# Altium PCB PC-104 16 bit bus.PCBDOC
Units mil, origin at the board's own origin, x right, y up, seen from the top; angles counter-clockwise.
Board outline 3550 x 3775 mil, 10 copper layers (TopLayer, MidLayer1, MidLayer2, MidLayer3, MidLayer4, MidLayer5, MidLayer6, MidLayer7, MidLayer8, BottomLayer); 2 components, 1 nets, 108 pads, 0 vias.
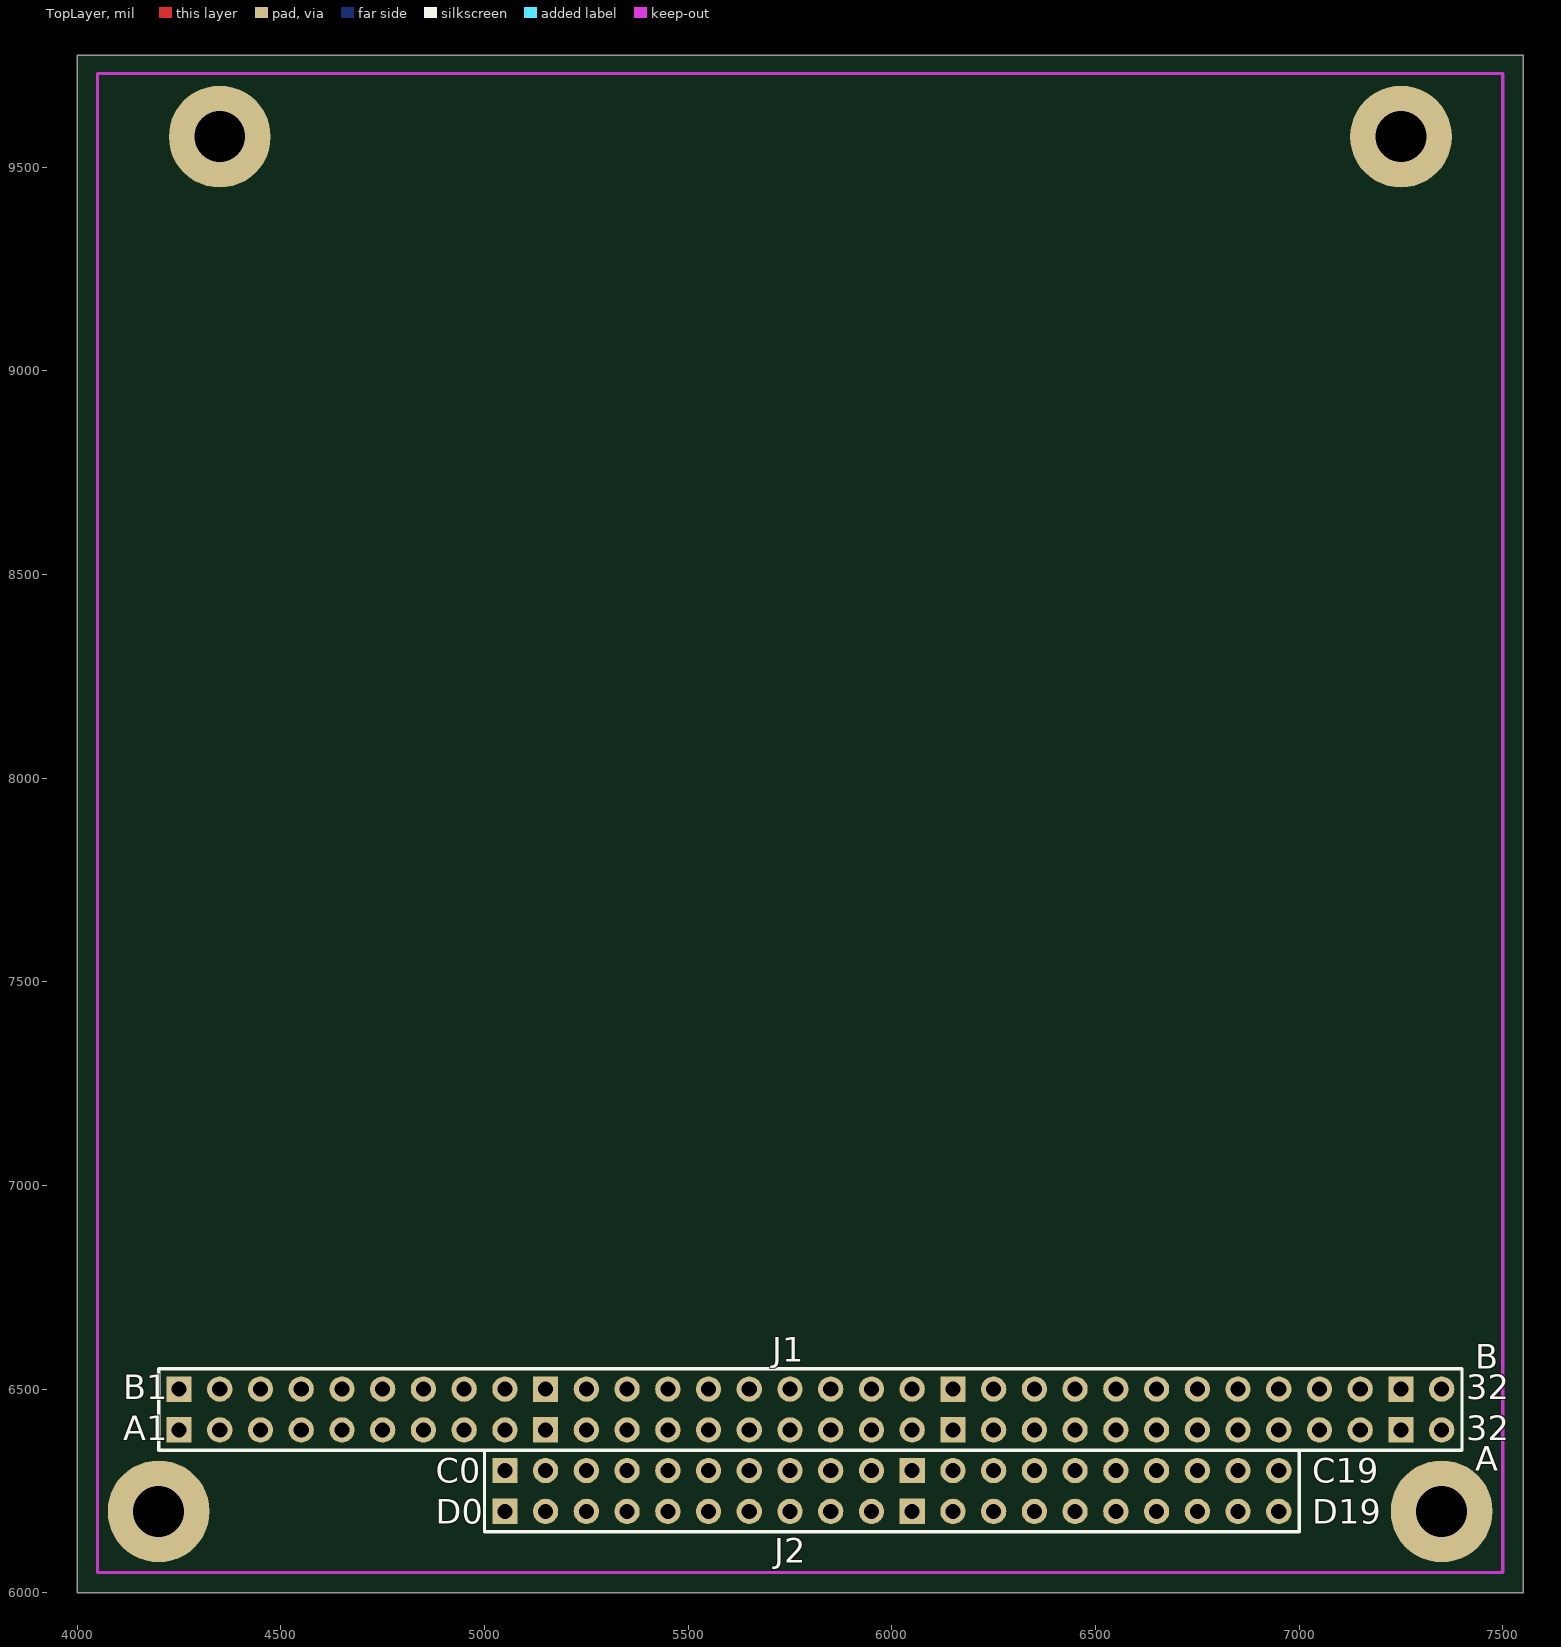
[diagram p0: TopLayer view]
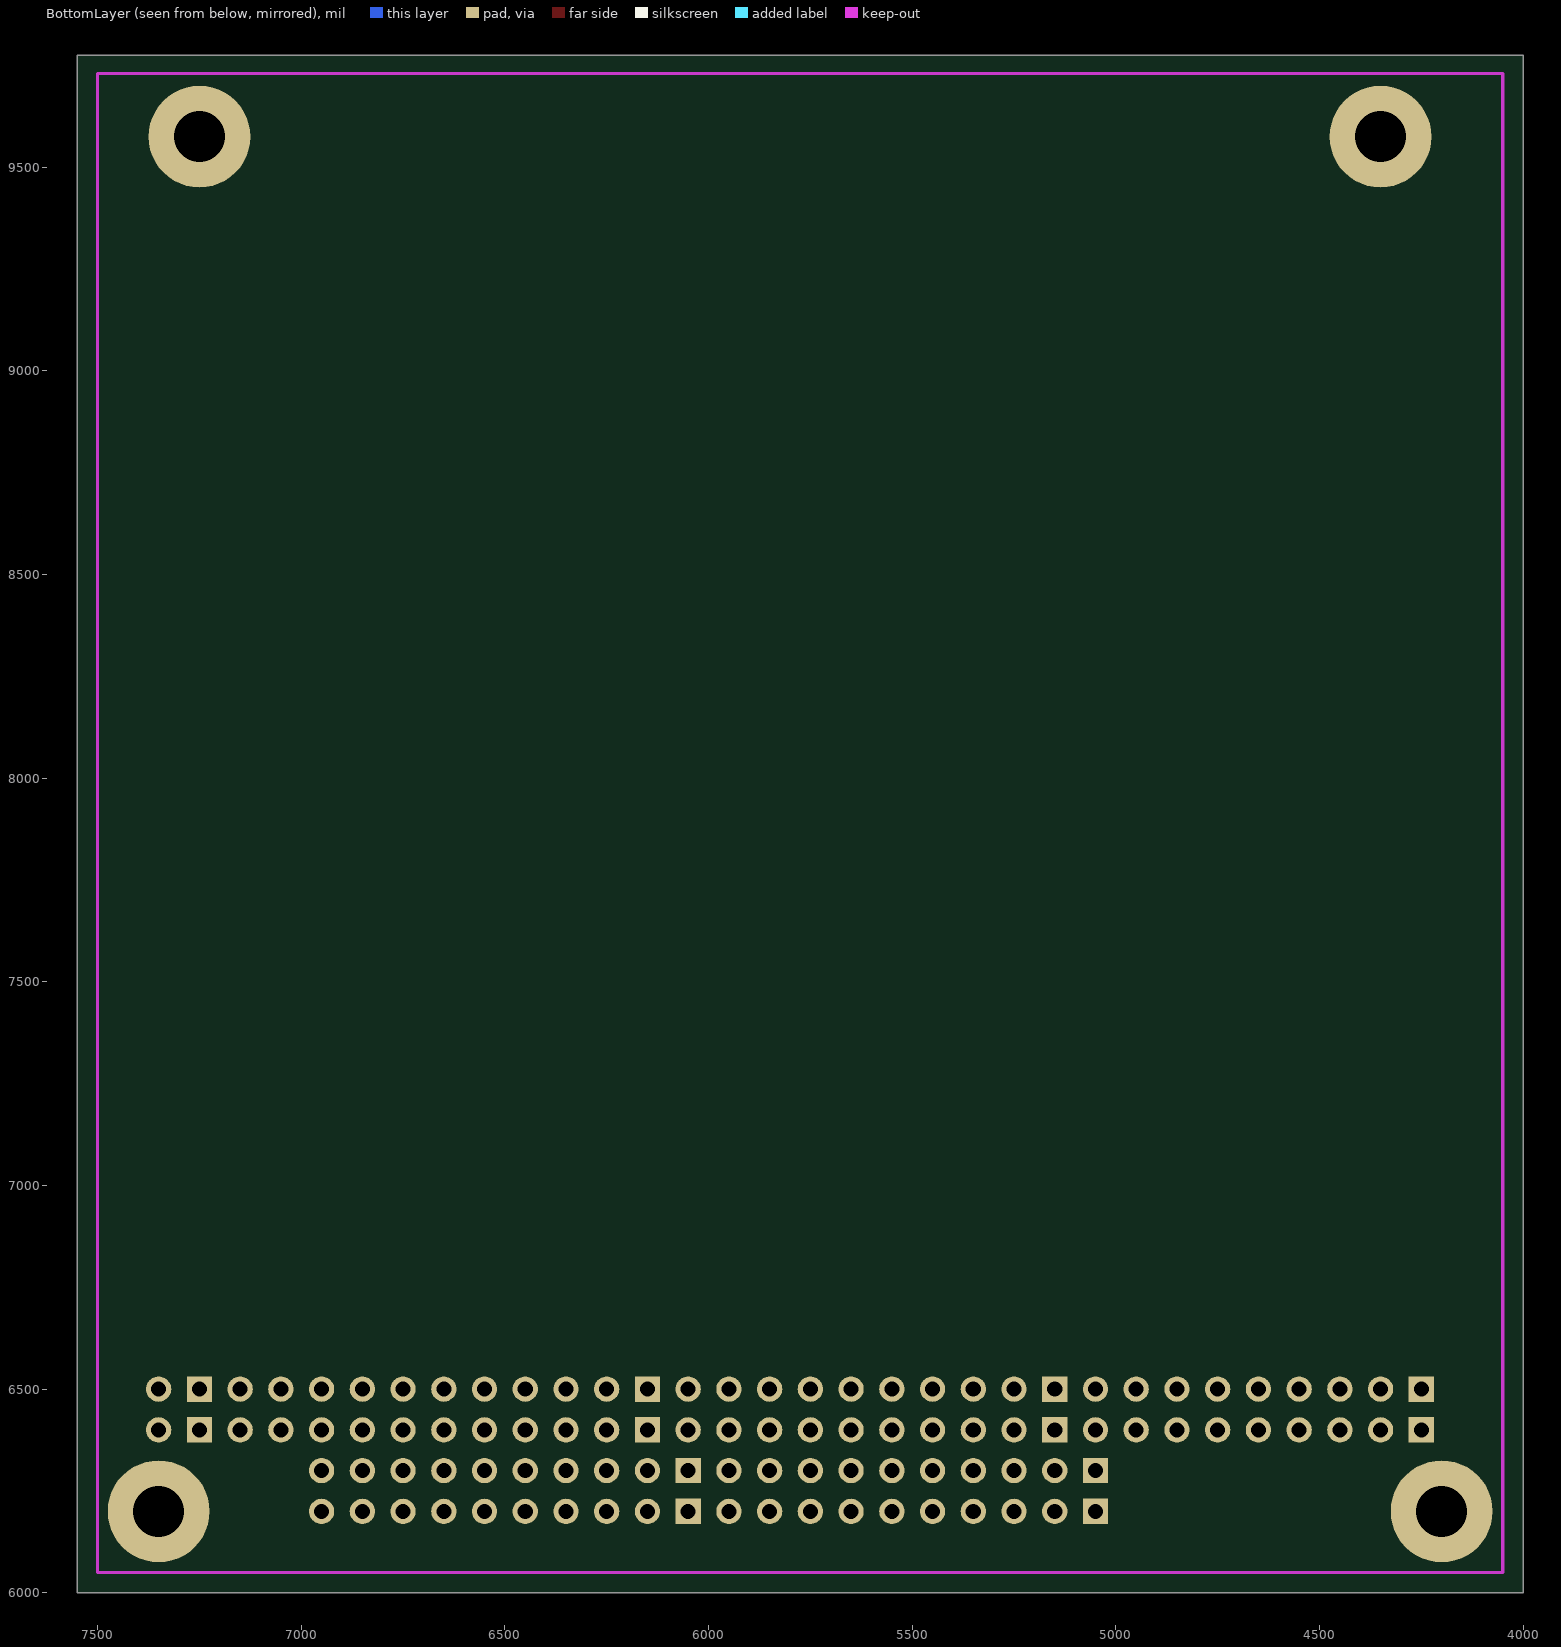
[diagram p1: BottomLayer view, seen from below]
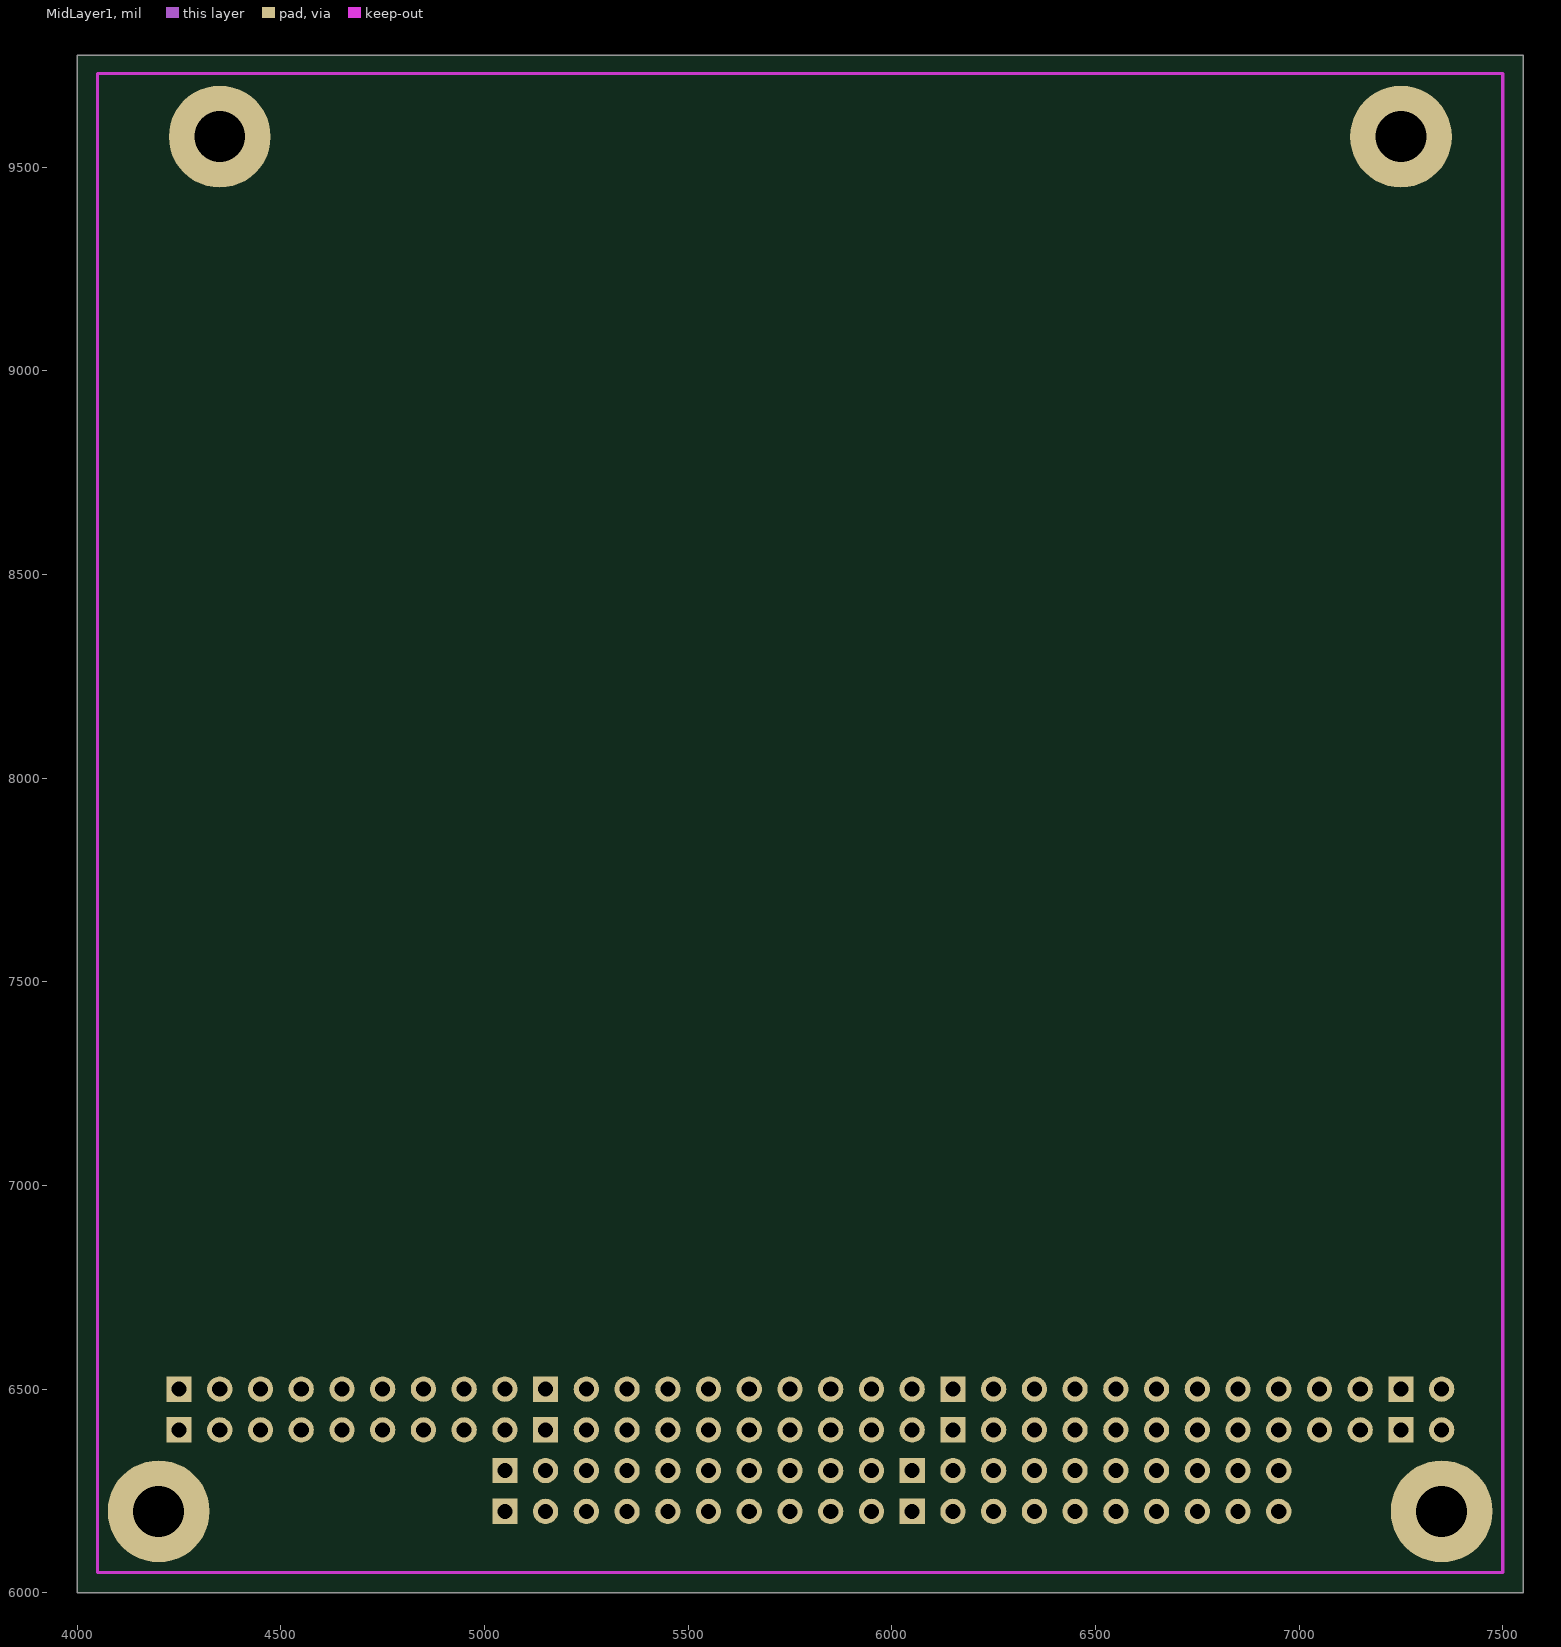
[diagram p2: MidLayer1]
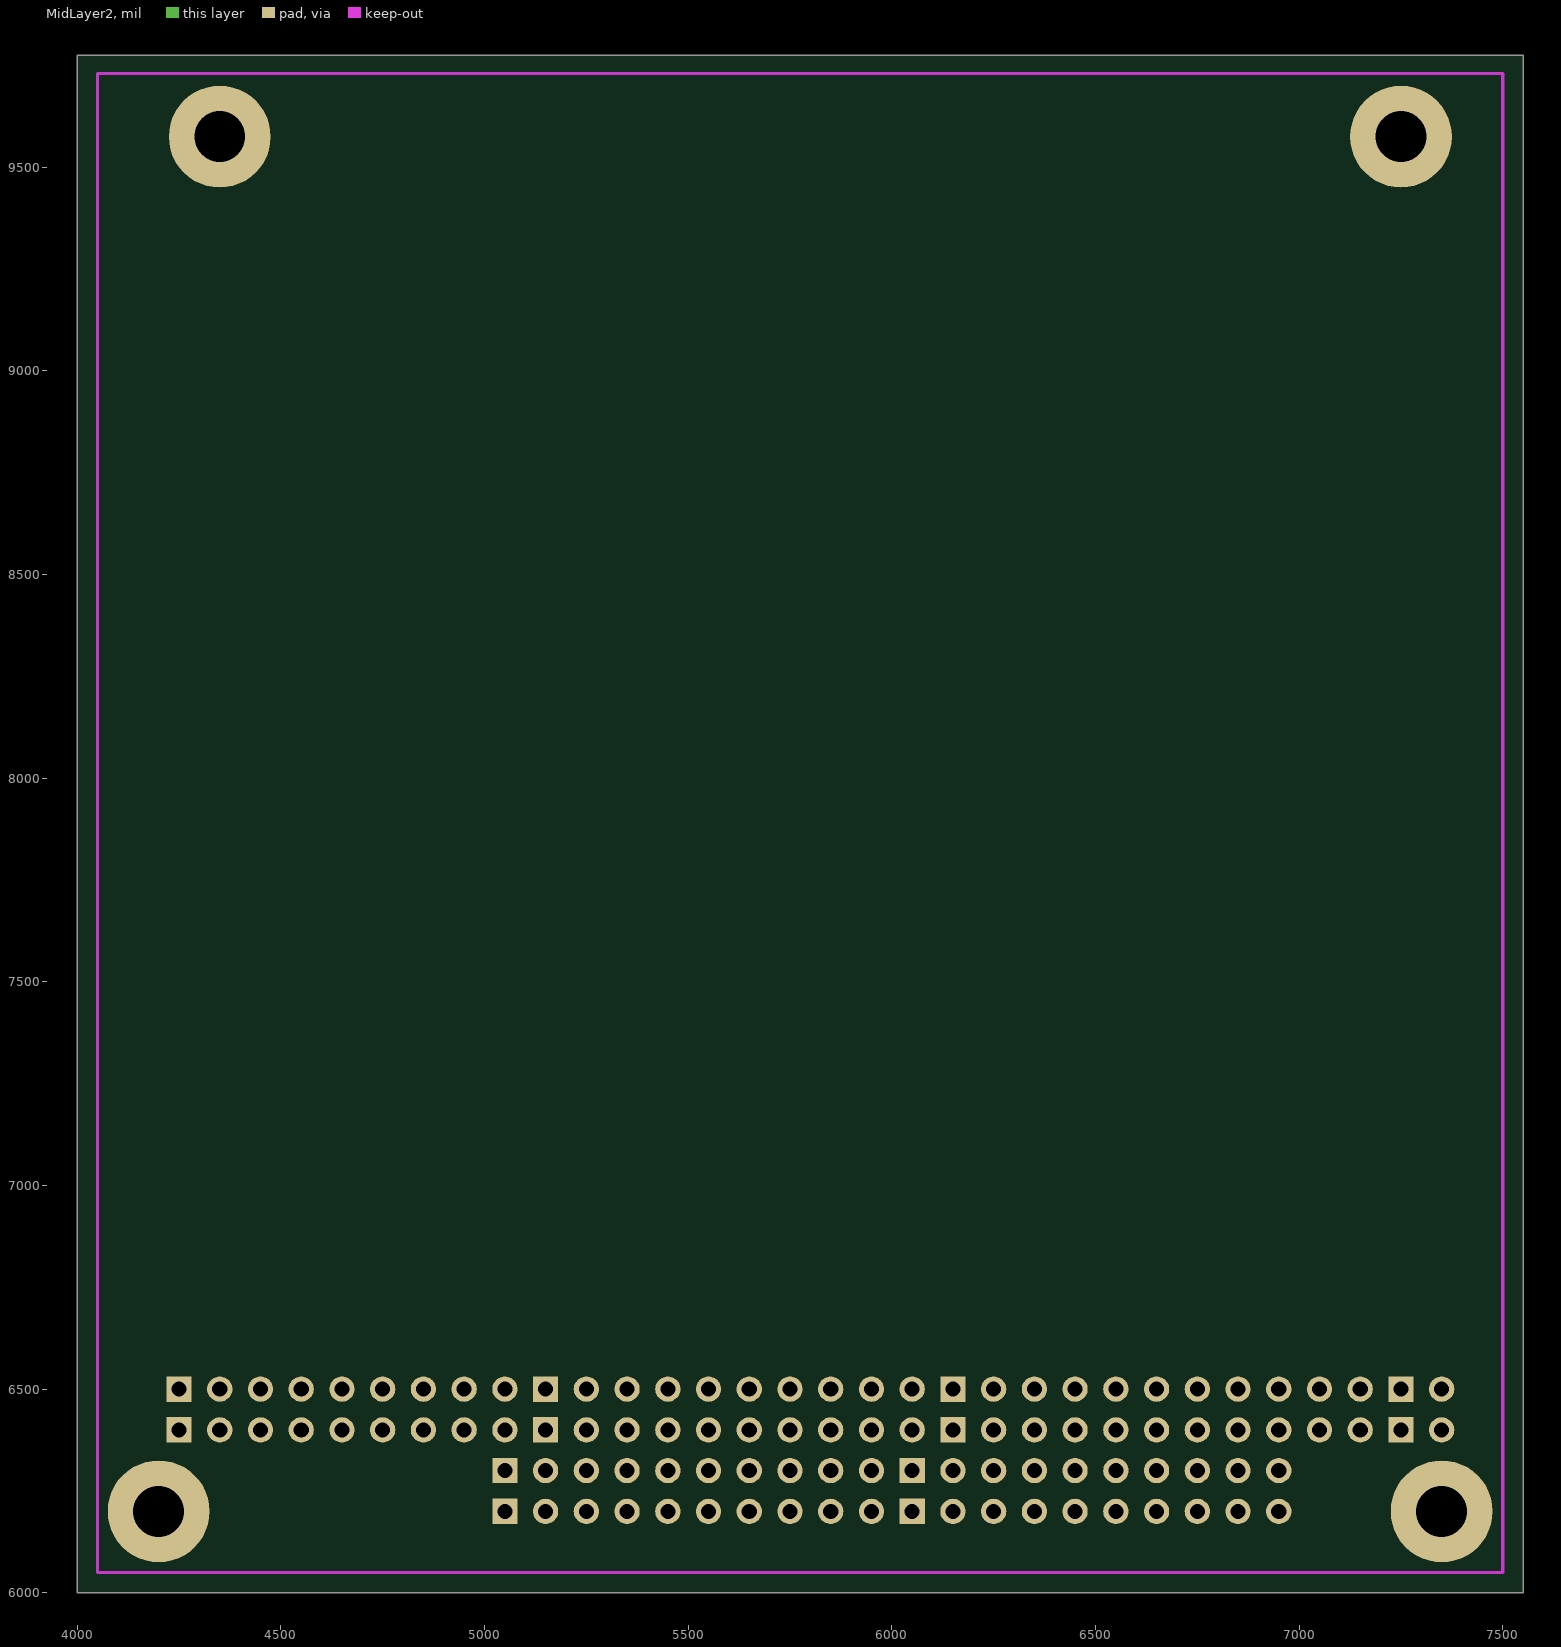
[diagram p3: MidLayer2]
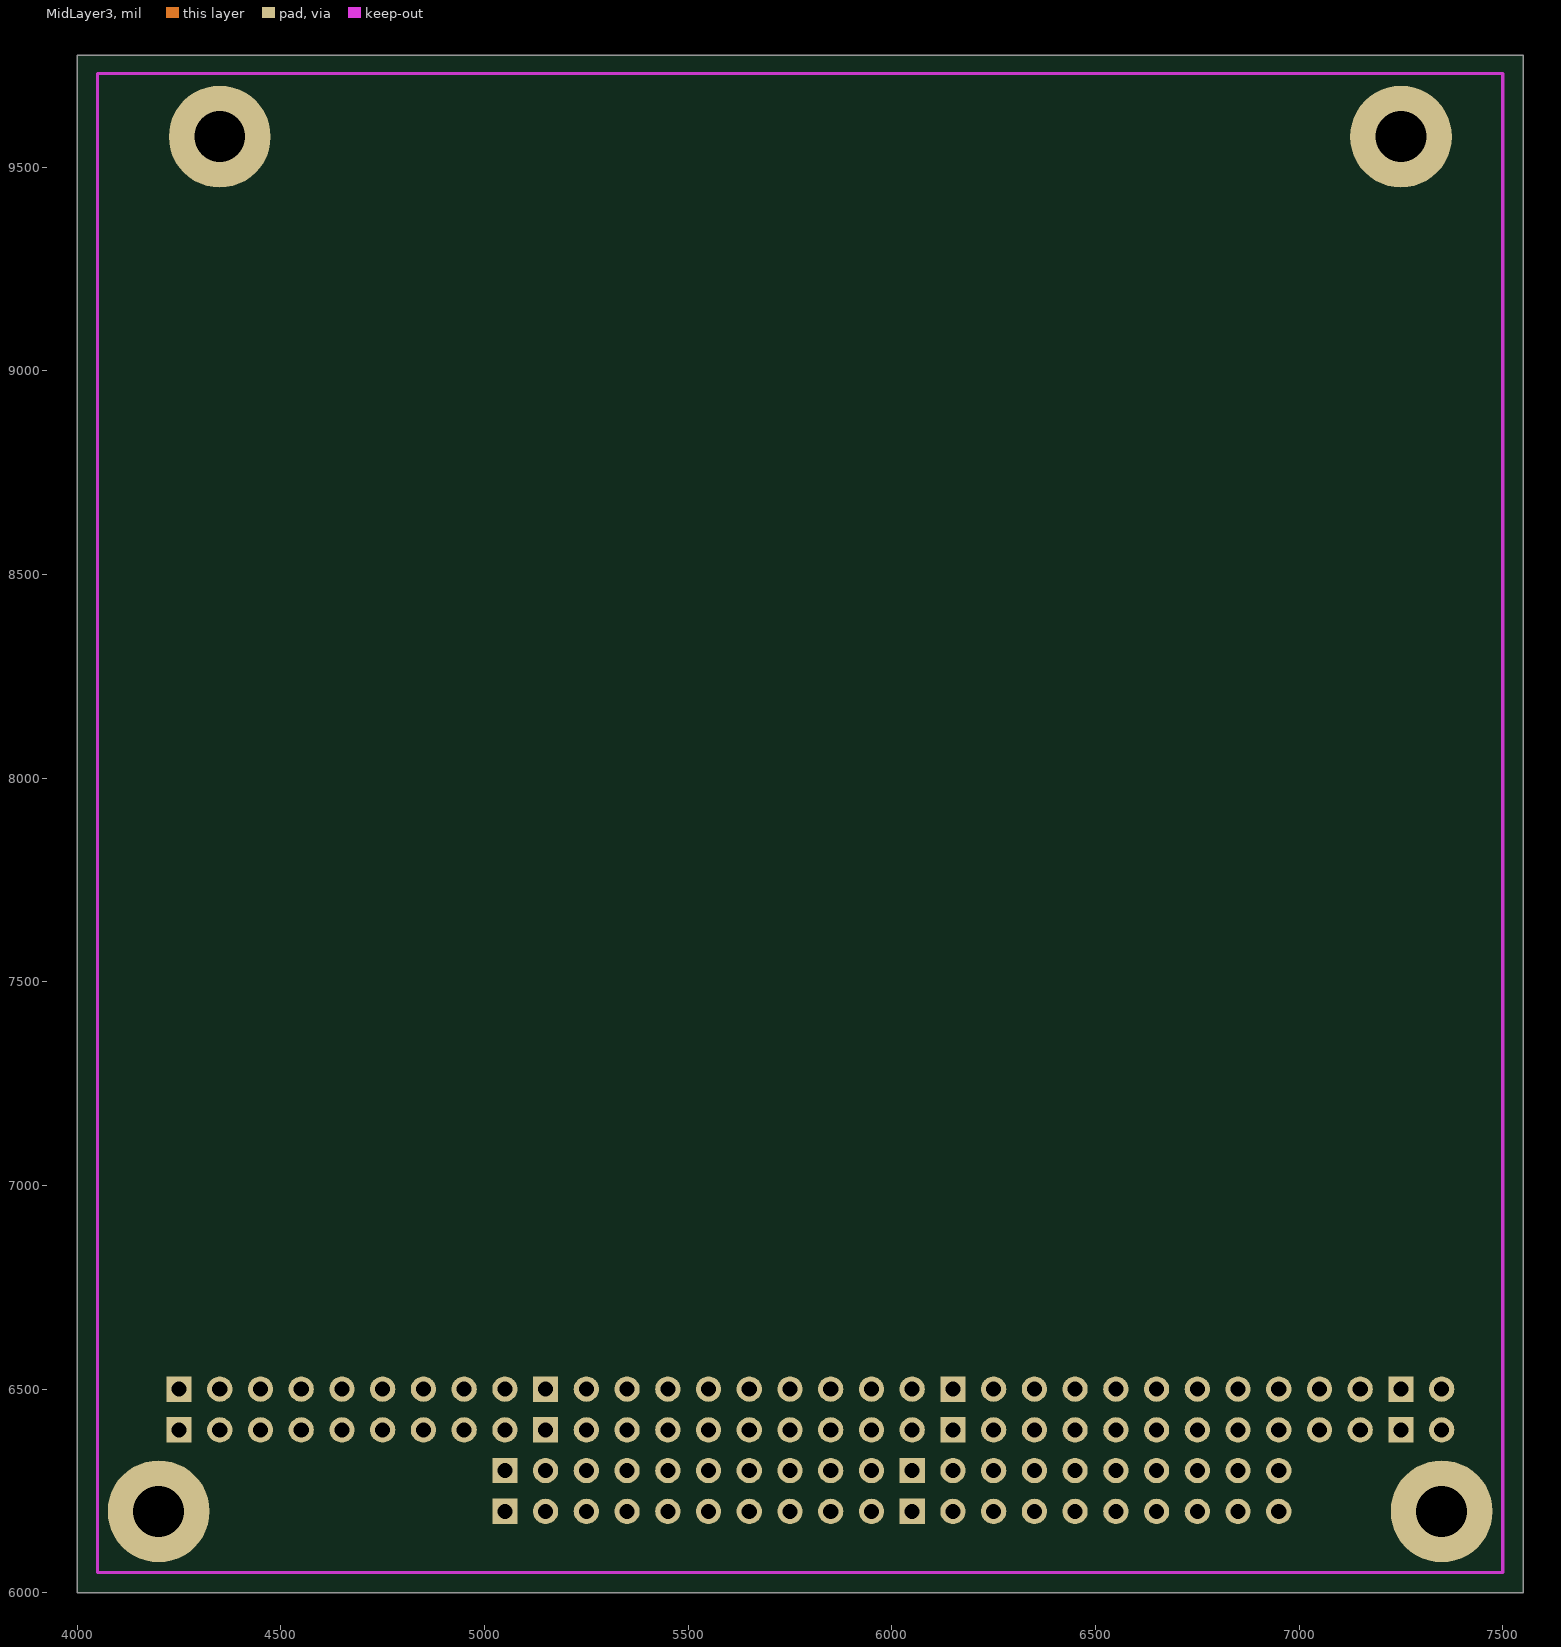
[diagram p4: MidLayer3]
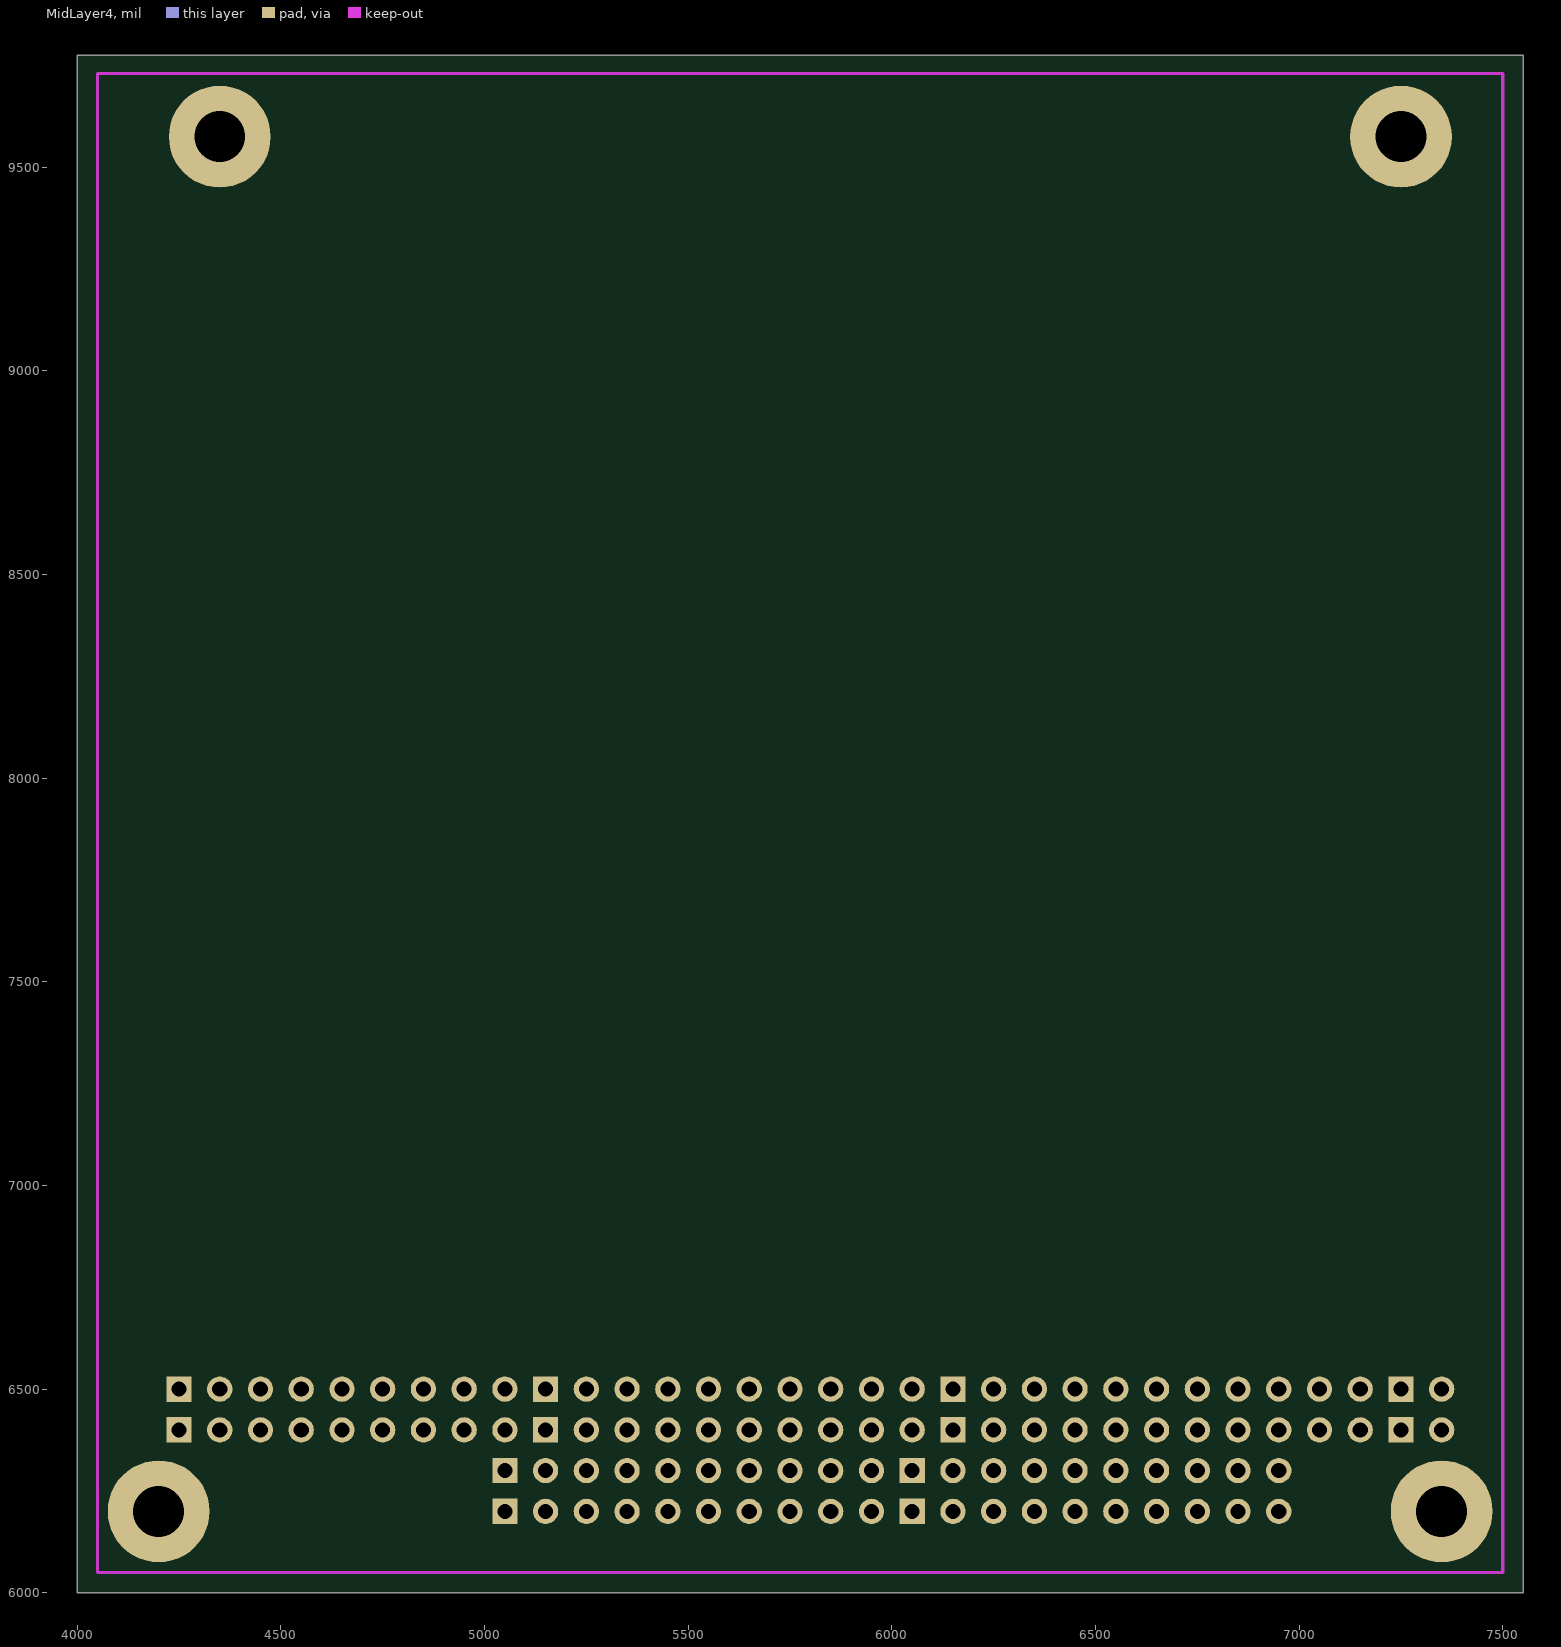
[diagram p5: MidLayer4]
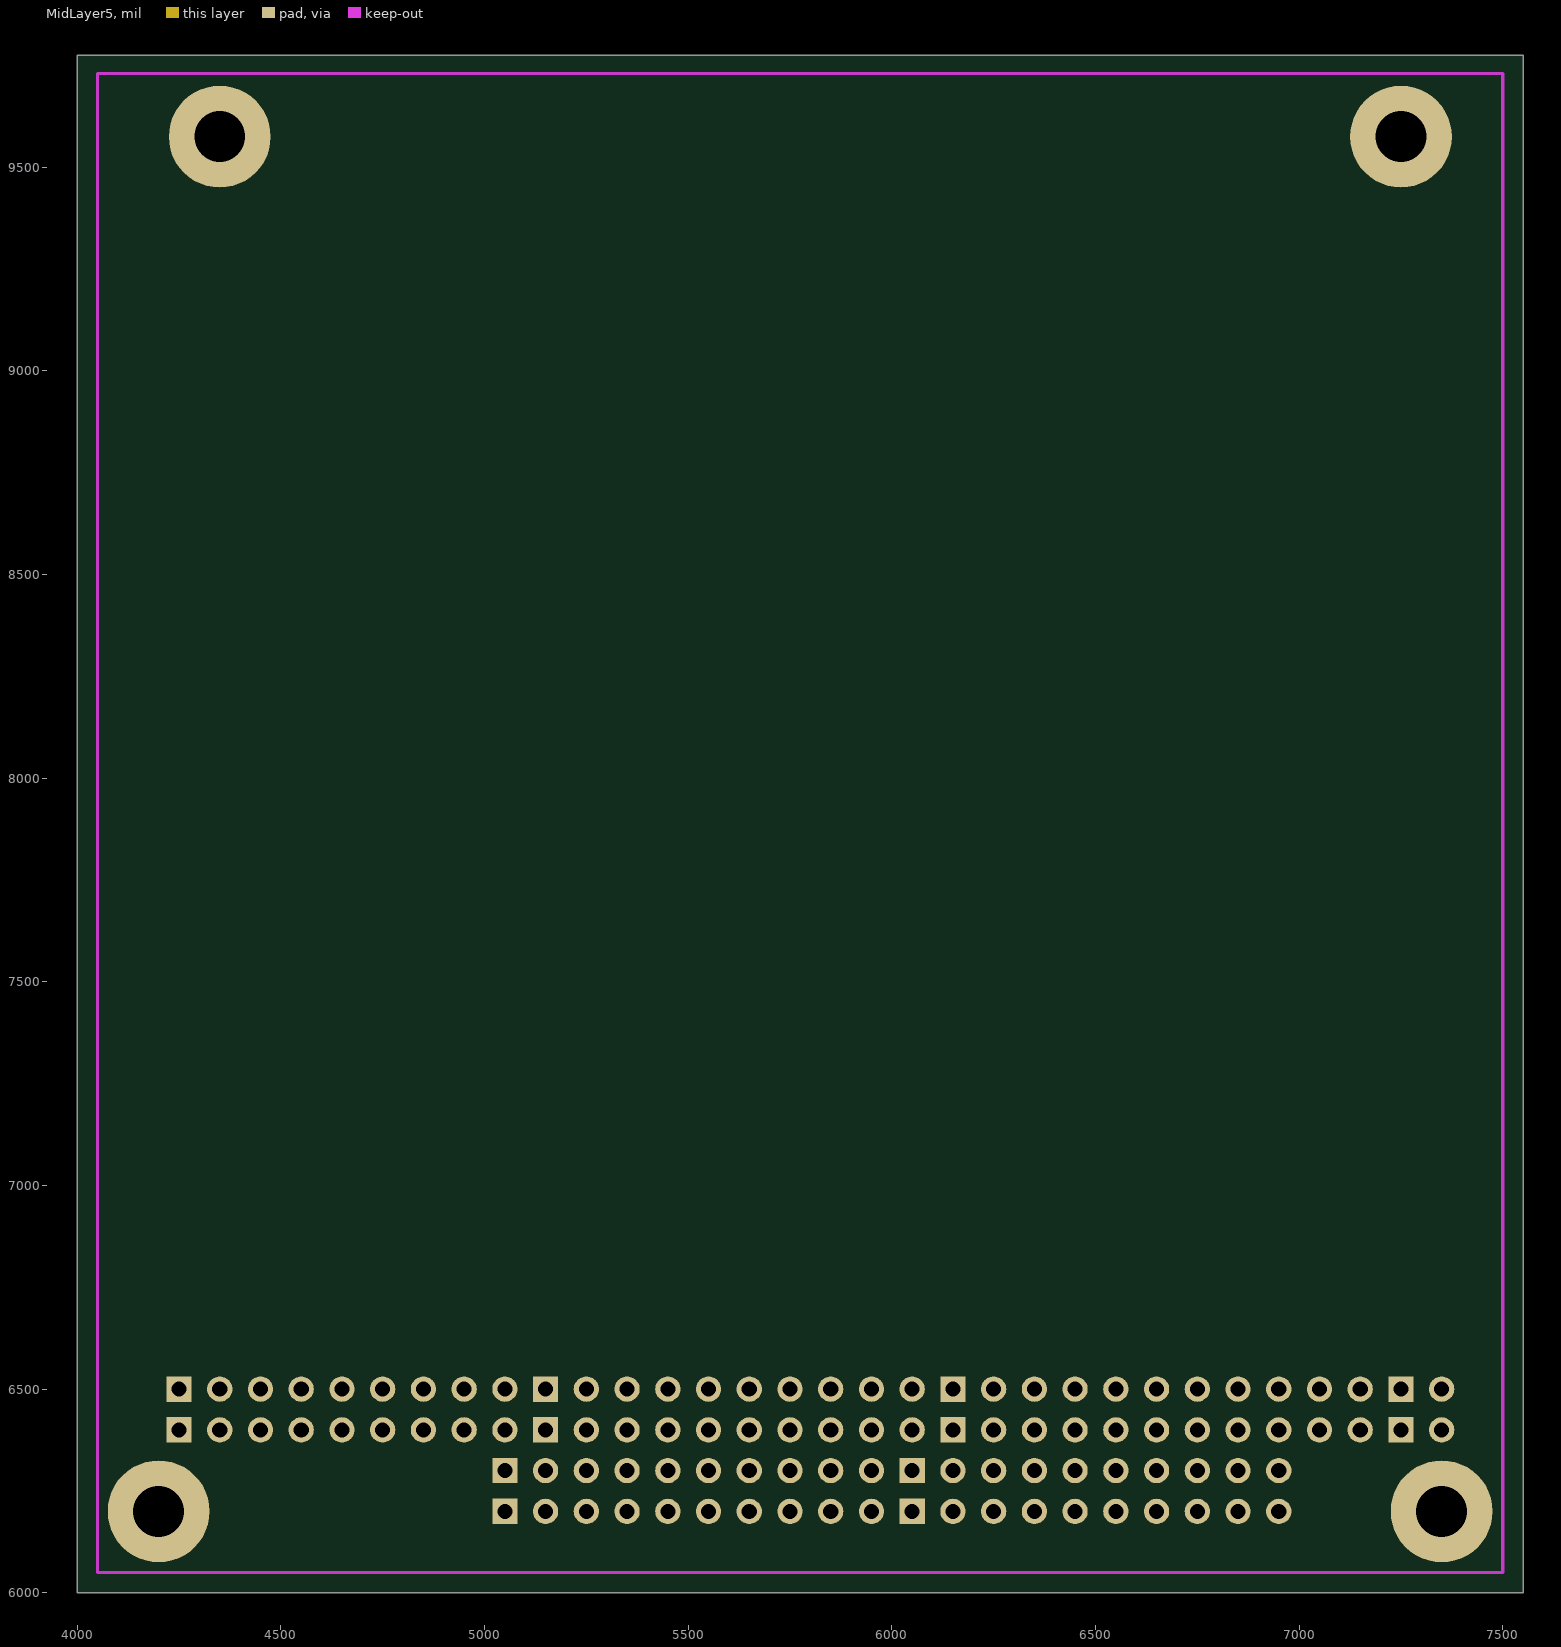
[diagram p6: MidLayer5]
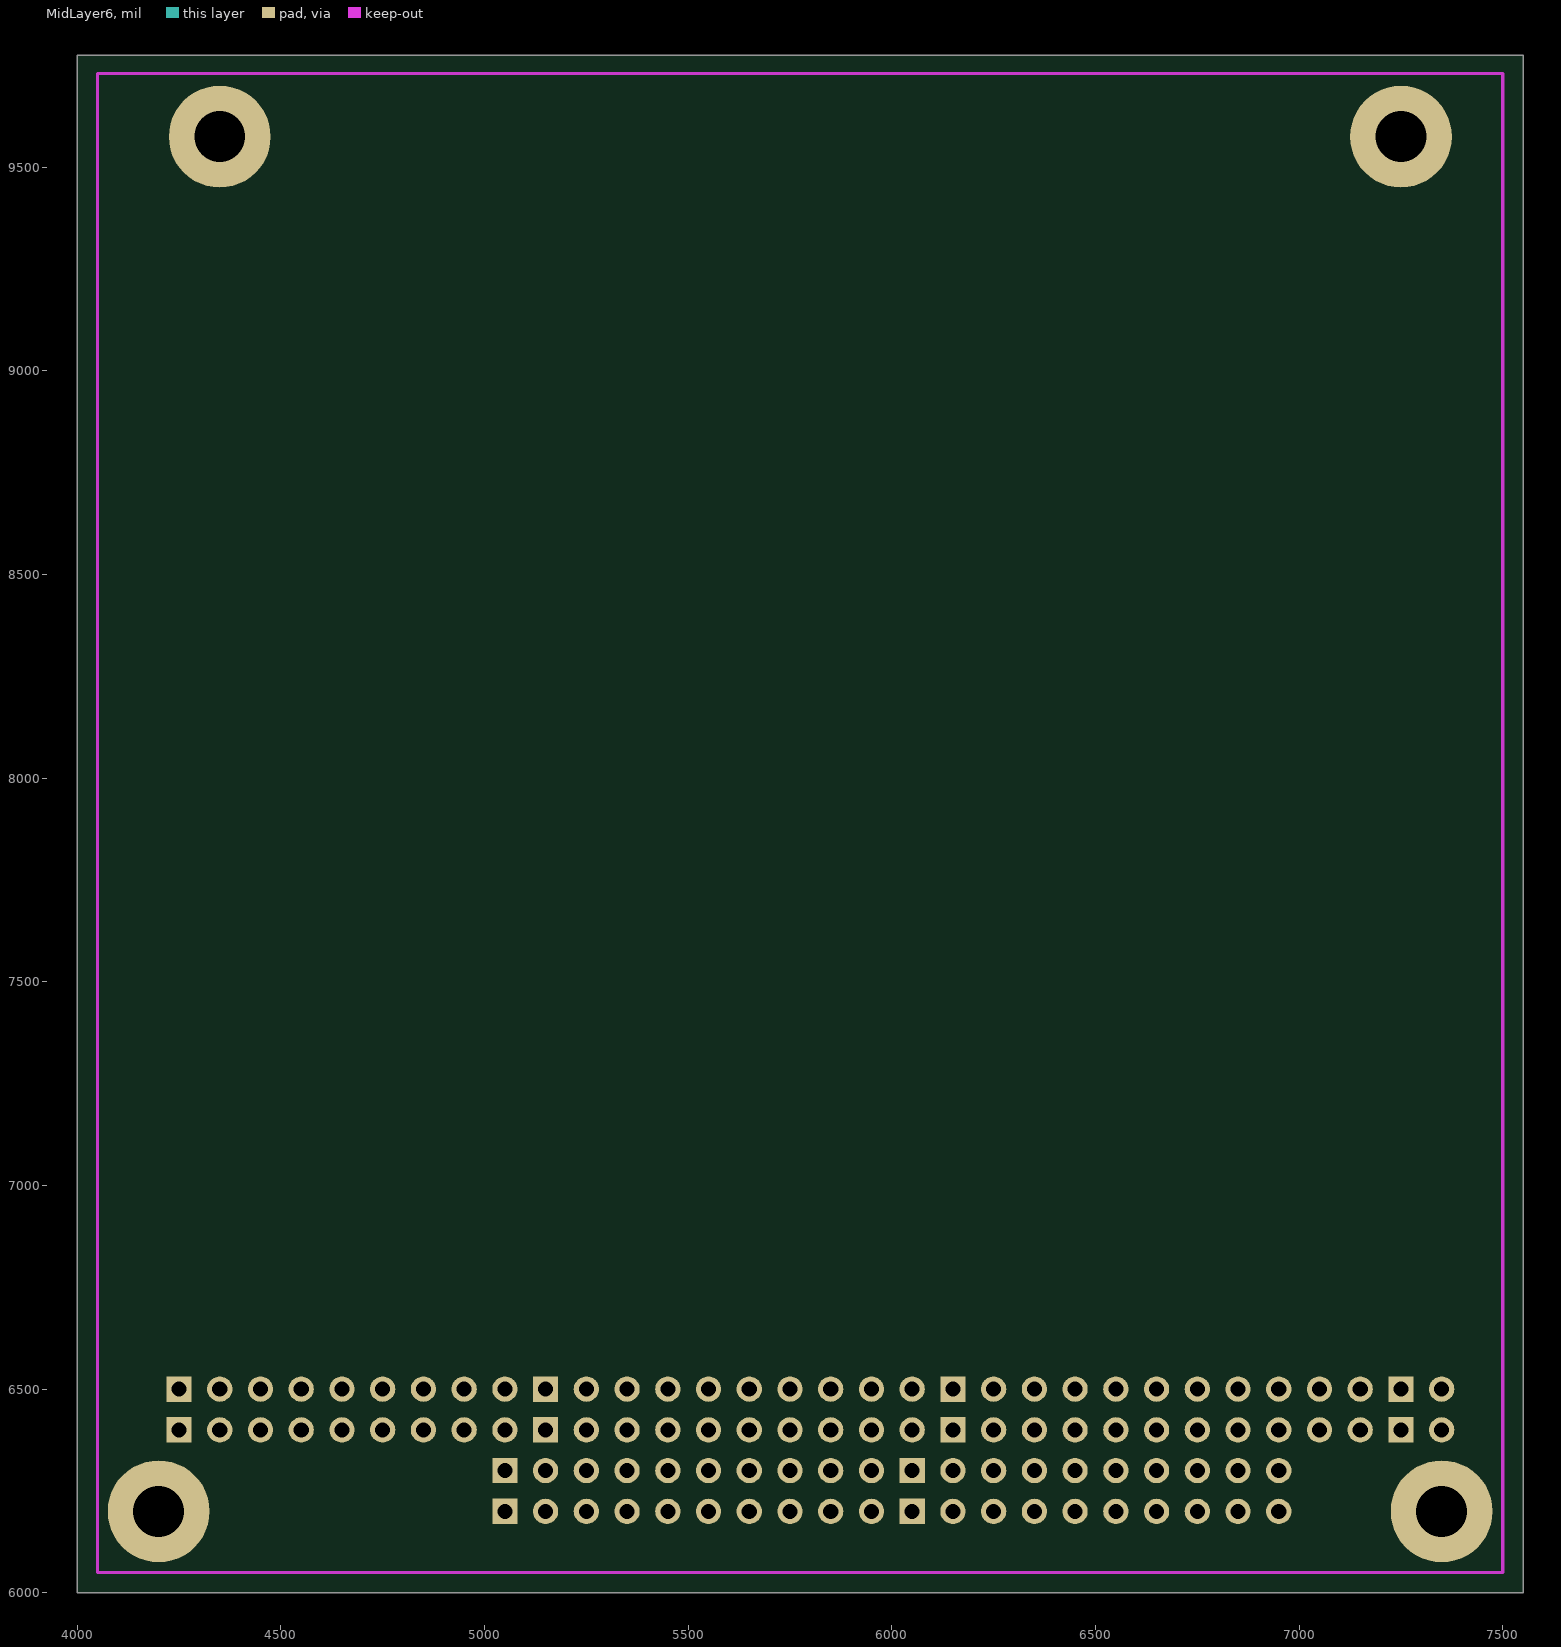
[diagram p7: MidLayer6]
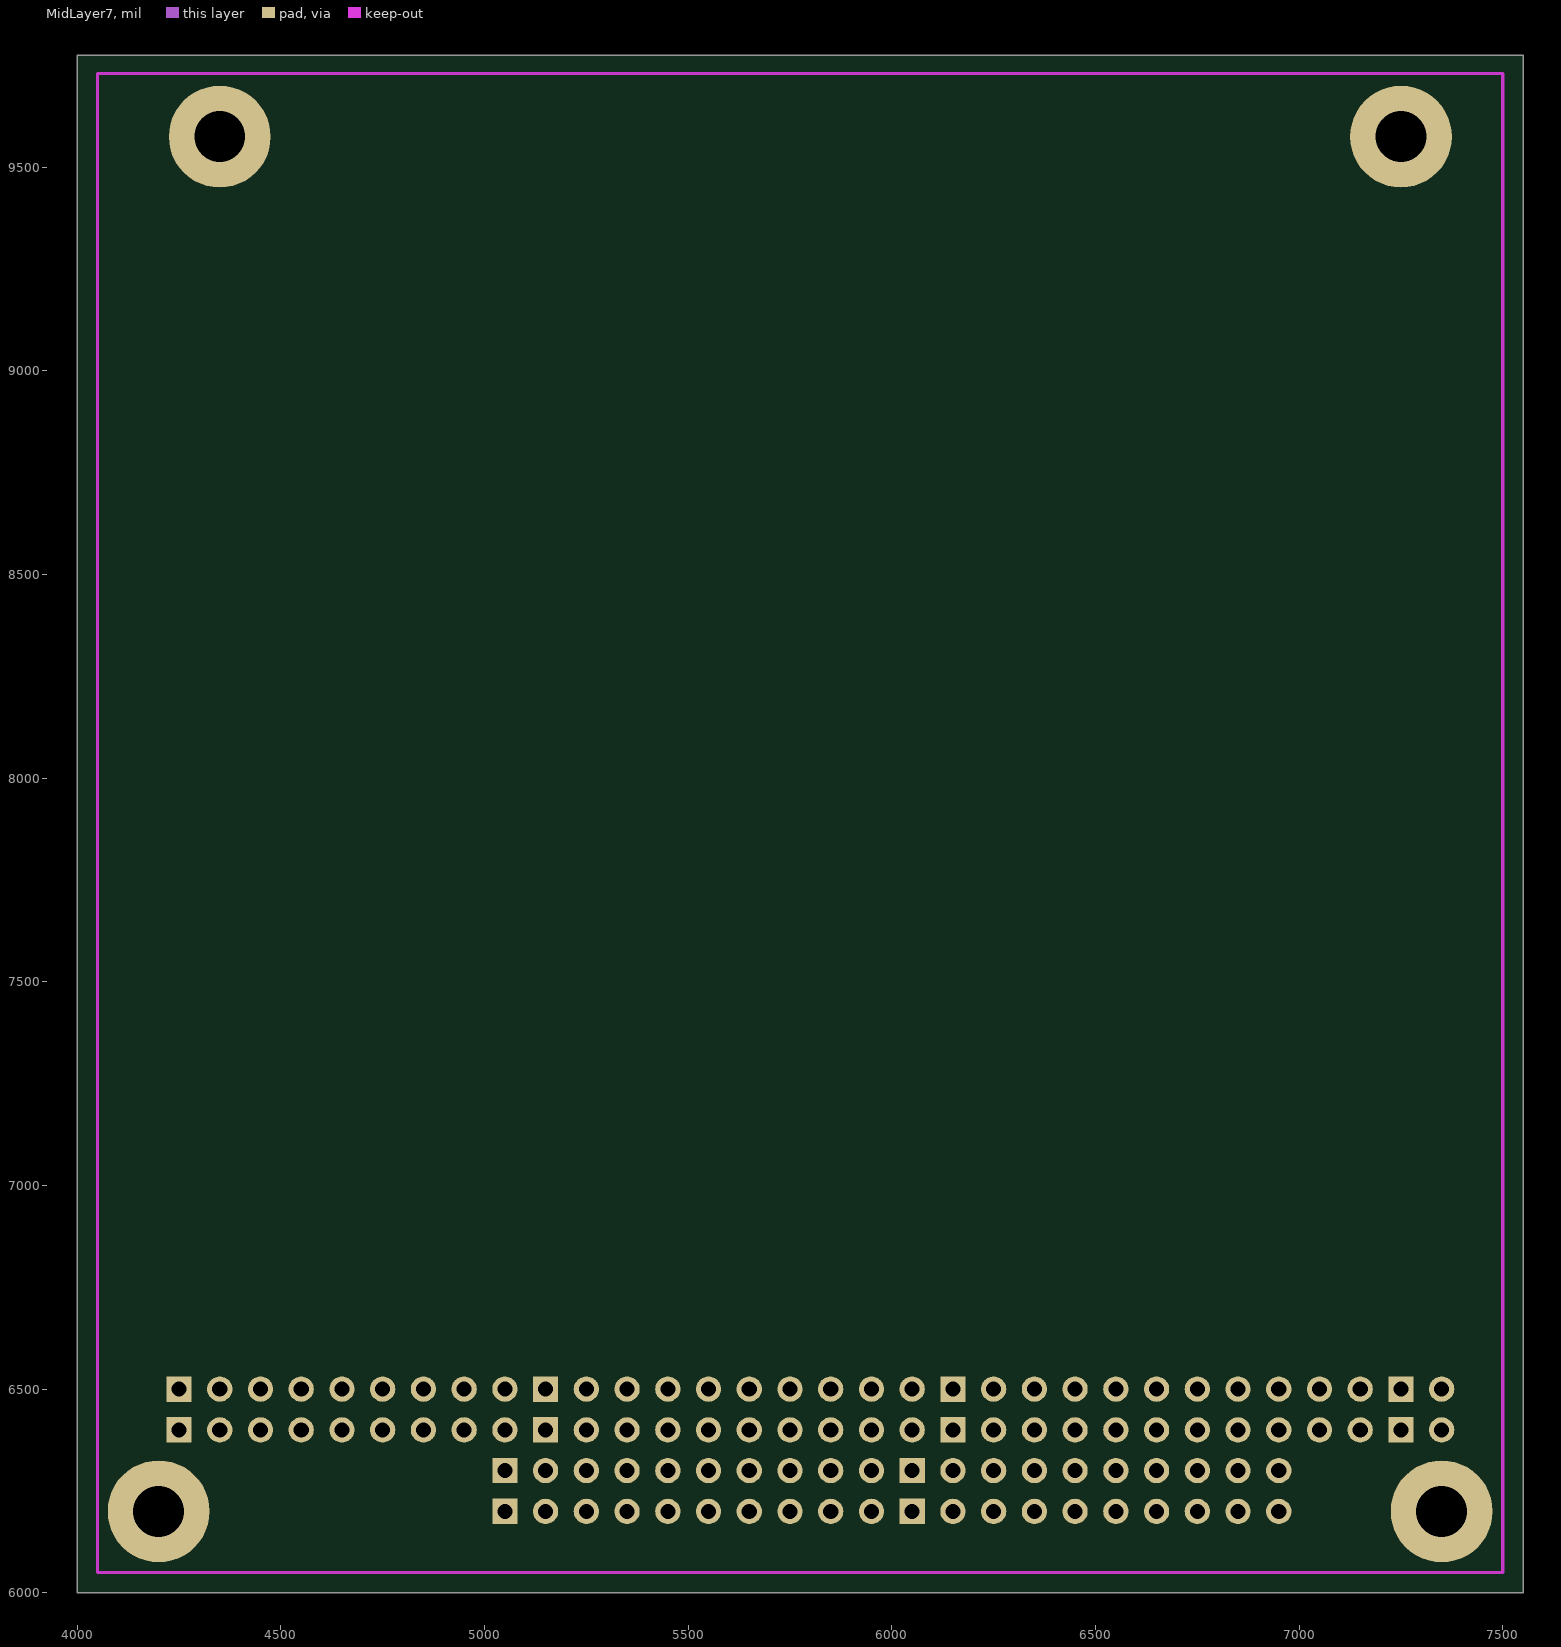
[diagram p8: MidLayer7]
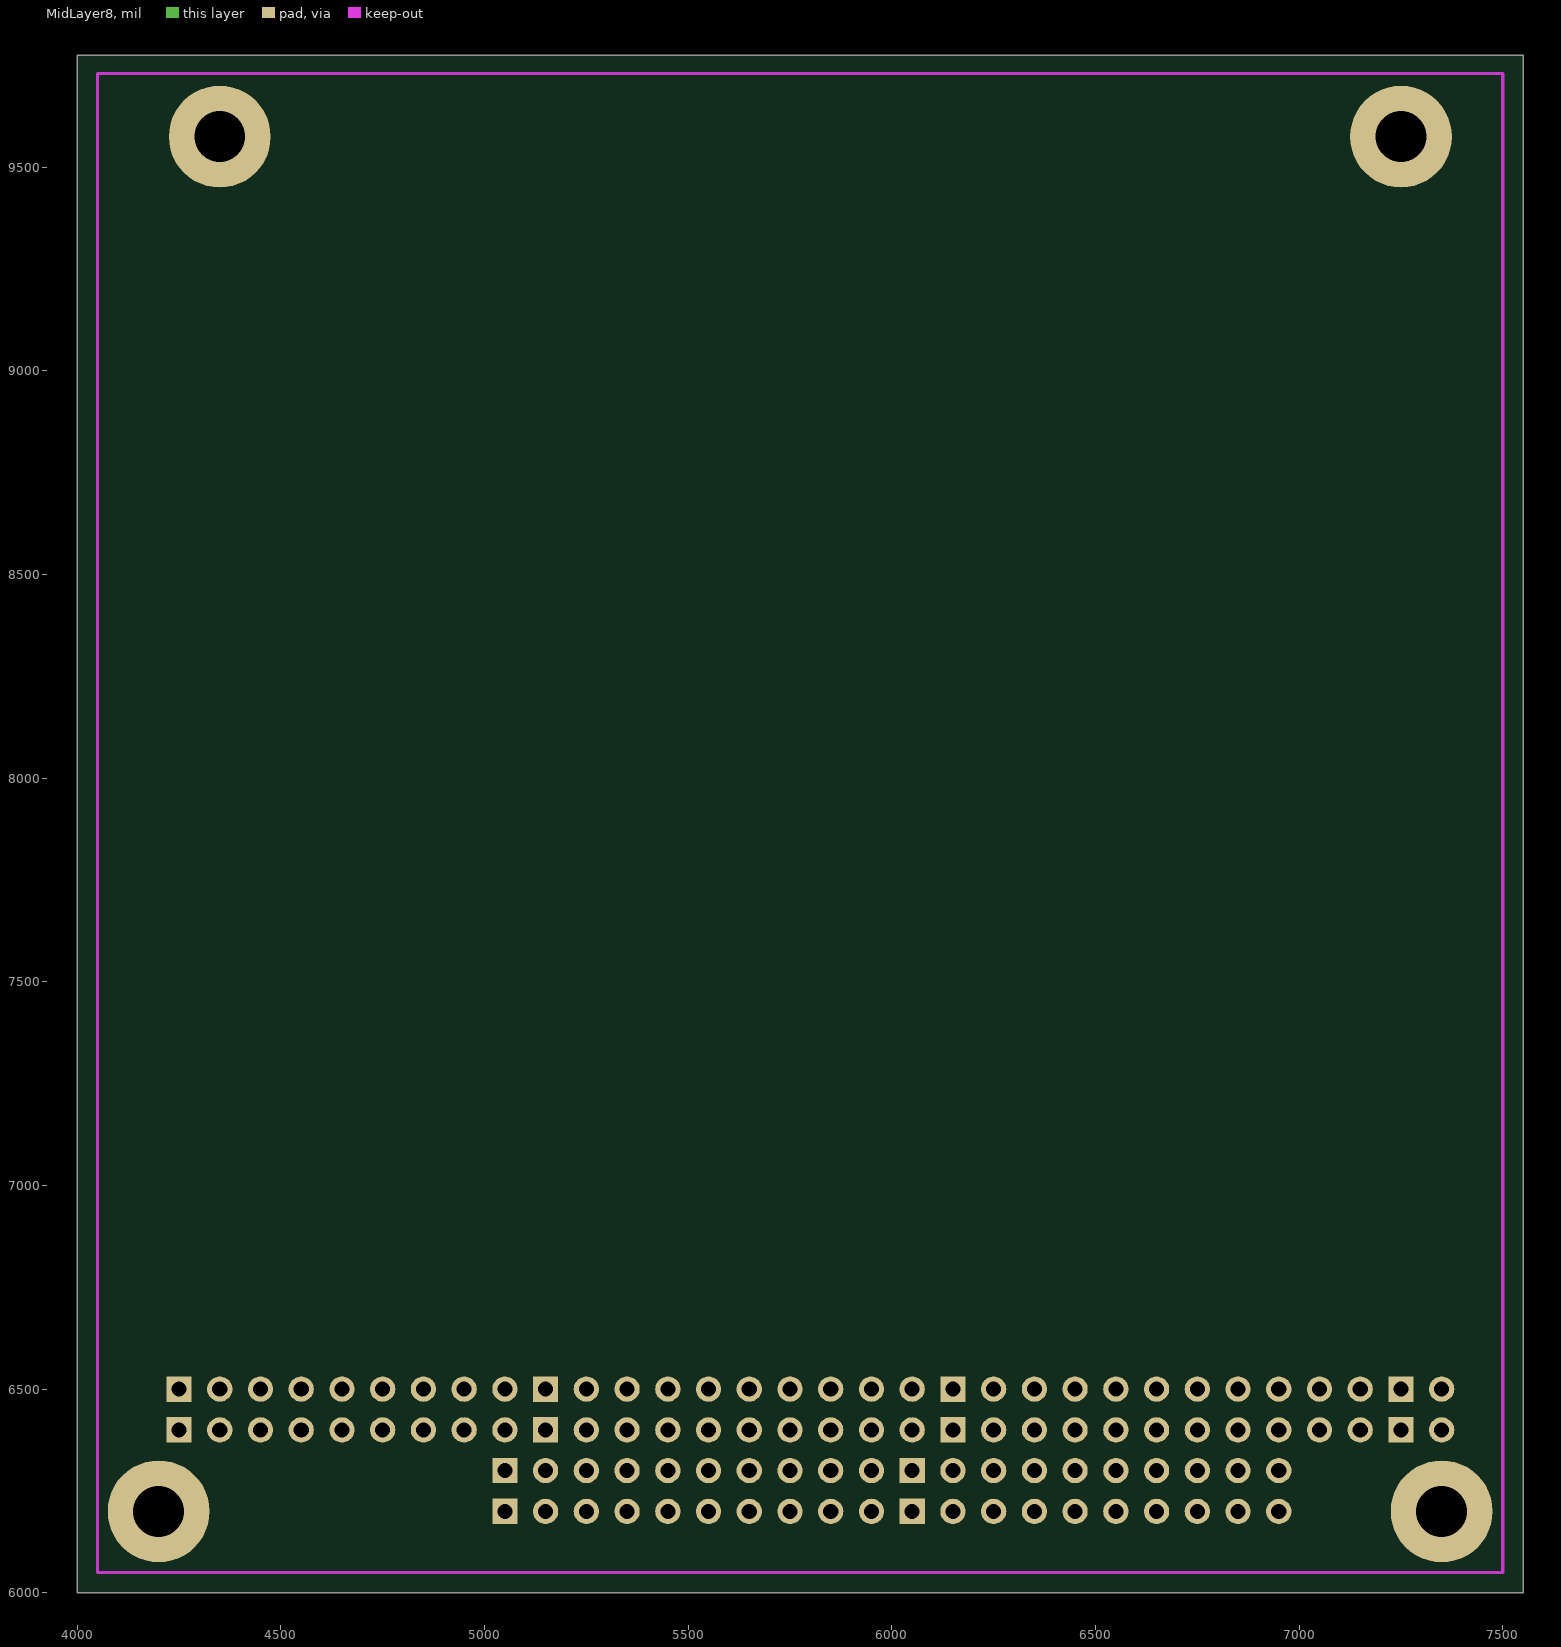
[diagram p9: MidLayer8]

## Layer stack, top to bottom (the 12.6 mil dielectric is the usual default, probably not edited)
TopSolder: solder mask 0.4, Solder Resist, Dk 3.5
TopLayer: signal copper 1.4
Dielectric1: core 12.6, FR-4, Dk 4.8
MidLayer1: signal copper 1.4
Dielectric2: prepreg 12.6, FR-4, Dk 4.8
MidLayer2: signal copper 1.4
Dielectric3: core 12.6, FR-4, Dk 4.8
MidLayer3: signal copper 1.4
Dielectric4: prepreg 12.6, FR-4, Dk 4.8
MidLayer4: signal copper 1.4
Dielectric5: core 12.6, FR-4, Dk 4.8
MidLayer5: signal copper 1.4
Dielectric6: prepreg 12.6, FR-4, Dk 4.8
MidLayer6: signal copper 1.4
Dielectric7: core 12.6, FR-4, Dk 4.8
MidLayer7: signal copper 1.4
Dielectric8: prepreg 12.6, FR-4, Dk 4.8
MidLayer8: signal copper 1.4
Dielectric9: core 12.6, FR-4, Dk 4.8
BottomLayer: signal copper 1.4
BottomSolder: solder mask 0.4, Solder Resist, Dk 3.5

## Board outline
4000,6000 7550,6000 7550,9775 4000,9775

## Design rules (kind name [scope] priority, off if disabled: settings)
Clearance [All] p1: gap=10
FabricationTestPointUsage TestPointUsage [All] p1: valid=0 allowmultiple=FALSE
FabricationTestpoint Testpoint [All] p1: side=3 testpointundercomponent=TRUE minsize=40 maxsize=100 preferedsize=60 minholesize=20 maxholesize=40 preferedholesize=32 testpointgrid=1 allowsidetop=TRUE allowsidebottom=TRUE usegrid=TRUE gridtolerance=0.01
PlaneClearance [All] p1: clearance=0
PolygonConnect [All] p1: connectstyle=Relief reliefconductorwidth=10 reliefentries=4 polygonreliefangle="90 Angle" airgapwidth=10
RoutingVias [All] p1: holewidth=20 width=50 viastyle="Through Hole" minholewidth=28 minwidth=50 maxholewidth=28 maxwidth=50
SilkToSolderMaskClearance SilkscreenOverComponentPads [IsPad] p1: minsilkscreentomaskgap=10 clearancetoexposedcopper=TRUE
SolderMaskExpansion [All] p1: expansion=4
Width [All] p1: maxlimit=10 minlimit=10 preferedwidth=10
26 further rules are at their usual default settings.

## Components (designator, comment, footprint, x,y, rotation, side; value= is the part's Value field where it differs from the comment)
J1 "" PC104AB 4250,6400 r0 top locked
J2 "" PC104CD 5050,6300 r0 top locked

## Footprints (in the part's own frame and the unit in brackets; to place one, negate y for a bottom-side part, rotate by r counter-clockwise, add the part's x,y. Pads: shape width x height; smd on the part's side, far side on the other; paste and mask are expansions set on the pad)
PC104AB [mil]
  rect 62x62 hole 37: A1(0,0) A10(900,0) A20(1900,0) A31(3000,0) B1(0,100) B10(900,100) B20(1900,100) B31(3000,100)
  round 62 hole 37: A2(100,0) A3(200,0) A4(300,0) A5(400,0) A6(500,0) A7(600,0) A8(700,0) A9(800,0) A11(1000,0) A12(1100,0) A13(1200,0) A14(1300,0) A15(1400,0) A16(1500,0) A17(1600,0) A18(1700,0) A19(1800,0) A21(2000,0) A22(2100,0) A23(2200,0) A24(2300,0) A25(2400,0) A26(2500,0) A27(2600,0) A28(2700,0) A29(2800,0) A30(2900,0) A32(3100,0) B2(100,100) B3(200,100) B4(300,100) B5(400,100) B6(500,100) B7(600,100) B8(700,100) B9(800,100) B11(1000,100) B12(1100,100) B13(1200,100) B14(1300,100) B15(1400,100) B16(1500,100) B17(1600,100) B18(1700,100) B19(1800,100) B21(2000,100) B22(2100,100) B23(2200,100) B24(2300,100) B25(2400,100) B26(2500,100) B27(2600,100) B28(2700,100) B29(2800,100) B30(2900,100) B32(3100,100)
  silkscreen extent -50,-50 3150,150
PC104CD [mil]
  rect 62x62 hole 37: C0(0,0) C10(1000,0) D0(0,-100) D10(1000,-100)
  round 62 hole 37: C1(100,0) C2(200,0) C3(300,0) C4(400,0) C5(500,0) C6(600,0) C7(700,0) C8(800,0) C9(900,0) C11(1100,0) C12(1200,0) C13(1300,0) C14(1400,0) C15(1500,0) C16(1600,0) C17(1700,0) C18(1800,0) C19(1900,0) D1(100,-100) D2(200,-100) D3(300,-100) D4(400,-100) D5(500,-100) D6(600,-100) D7(700,-100) D8(800,-100) D9(900,-100) D11(1100,-100) D12(1200,-100) D13(1300,-100) D14(1400,-100) D15(1500,-100) D16(1600,-100) D17(1700,-100) D18(1800,-100) D19(1900,-100)
  silkscreen extent -50,-150 1950,50

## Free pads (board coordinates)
  round 250 hole 125: 1(4200,6200) 2(7250,9575) 3(7350,6200) 4(4350,9575)

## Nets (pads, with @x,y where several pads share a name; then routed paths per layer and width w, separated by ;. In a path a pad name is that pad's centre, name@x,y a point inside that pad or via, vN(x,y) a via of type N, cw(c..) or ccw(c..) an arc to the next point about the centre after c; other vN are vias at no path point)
"": 
pads on no net: J1.A1 J1.A2 J1.A3 J1.A4 J1.A5 J1.A6 J1.A7 J1.A8 J1.A9 J1.A10 J1.A11 J1.A12 J1.A13 J1.A14 J1.A15 J1.A16 J1.A17 J1.A18 J1.A19 J1.A20 J1.A21 J1.A22 J1.A23 J1.A24 J1.A25 J1.A26 J1.A27 J1.A28 J1.A29 J1.A30 J1.A31 J1.A32 J1.B1 J1.B2 J1.B3 J1.B4 J1.B5 J1.B6 J1.B7 J1.B8 J1.B9 J1.B10 J1.B11 J1.B12 J1.B13 J1.B14 J1.B15 J1.B16 J1.B17 J1.B18 J1.B19 J1.B20 J1.B21 J1.B22 J1.B23 J1.B24 J1.B25 J1.B26 J1.B27 J1.B28 J1.B29 J1.B30 J1.B31 J1.B32 J2.C0 J2.C1 J2.C2 J2.C3 J2.C4 J2.C5 J2.C6 J2.C7 J2.C8 J2.C9 J2.C10 J2.C11 J2.C12 J2.C13 J2.C14 J2.C15 J2.C16 J2.C17 J2.C18 J2.C19 J2.D0 J2.D1 J2.D2 J2.D3 J2.D4 J2.D5 J2.D6 J2.D7 J2.D8 J2.D9 J2.D10 J2.D11 J2.D12 J2.D13 J2.D14 J2.D15 J2.D16 J2.D17 J2.D18 J2.D19

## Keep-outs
KeepOutLayer:
  lines w8: 4050,6050 4050,9730 7500,9730 7500,6050 4050,6050

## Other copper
TopLayer:
  text ".GTL" at 7230,9908 h90
MidLayer1:
  text ".G1" at 7230,9908 h90
MidLayer2:
  text ".G2" at 7230,9908 h90
MidLayer3:
  text ".G3" at 7230,9908 h90
MidLayer4:
  text ".G4" at 7230,9908 h90
MidLayer5:
  text ".G5" at 7230,9908 h90
MidLayer6:
  text ".G6" at 7230,9908 h90
MidLayer7:
  text ".G7" at 7230,9908 h90
MidLayer8:
  text ".G8" at 7230,9908 h90
BottomLayer:
  text "P/N XXXXXX-XXX REV A" at 5320,10238 h75
  text ".GBL" at 7230,9908 h90

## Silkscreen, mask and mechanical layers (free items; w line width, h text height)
TopOverlay:
  rectangle: 4281,10731 5031,10931
  rectangle: 4281,10441 5031,10641
  lines w10: 5392.59,10833.97 ccw(c5441,10873.5) 5392.71,10833.83
  text "C" at 5496,10836 h60
  text "2002 COMPANY NAME" at 5646,10836 h75
  text "S/N" at 4031,10788.5 h75
  text "BOARD NAME" at 5496,10661 h75
  text "ASSY NO.: XXXXXX" at 5496,10511 h75
  text "REV" at 4031,10491 h75
  text ".GTO" at 7230,9908 h90
TopPaste:
  text ".GTP" at 7230,9908 h90
BottomPaste:
  text ".GBP" at 7230,9908 h90
TopSolder:
  text ".GTS" at 7230,9908 h90
BottomSolder:
  text ".GBS" at 7230,9908 h90
Mechanical1:
  the board outline again, w8
Mechanical4:
  text ".Pcb_File_Name_No_Path" at 5330,10098 h90
  text ".Printout_Name" at 5330,9928 h90
DrillDrawing:
  text ".LEGEND" at 7895,6220 h90
  text "Drilling Details." at 7895,6070 h90

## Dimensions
4200,5980 to 4000,6000 on Mechanical4
3980,6200 to 4000,6000 on Mechanical4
